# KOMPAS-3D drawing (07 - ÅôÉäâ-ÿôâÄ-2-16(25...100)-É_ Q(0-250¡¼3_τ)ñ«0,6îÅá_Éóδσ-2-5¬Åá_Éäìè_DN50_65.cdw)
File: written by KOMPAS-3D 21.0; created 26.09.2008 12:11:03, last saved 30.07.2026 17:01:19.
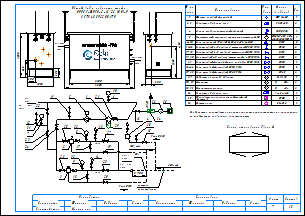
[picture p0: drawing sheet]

Sheets 1-2: A3, landscape

Document properties: Наименование: Макро:21; Автор: RaskoAdmin; Форматы листов документа: 2xA3; Полное имя файла: \\UR38nt01\Departments\КТО\КБ ПУРДГ\Заявки\Прайс-лист на типовые шкафы ГРПШ\ПУРДГ_стандарт_30_04_2026\ПУРДГ с РДНК\ПУРДГ-ШУГО-2-16(25...100)-Р_ Q(0-250нм3_ч)до0,6МПа_Рвых-2-5кПа_РДНК_DN50_65.cdw

Title block, sheet 1: Наименование: Пункт учета газа / ПУГ-Ш-400-Р / ЛГТИ.485922.001ТУ; designation: ЛГТИ.03.4411141; sheet number: 1; Количество листов документа: 2; organisation: ООО "ЭЛЬСТЕР Газэлектроника"; Форматы листов документа: A3; stored path: C:\Рабочие документы\Компас\ПУГ\Схема.cdw; Разработал: Устинов; Проверил: Кошкин; Утвердил: Кошкин
Title block, sheet 2: sheet number: 2; stored path: D:\Рабочие документы\Заявки\ПУРДГ\ПУРДГ-ШУЭО-2-100-Р 4411220.cdw; designation, second copy: ЛГТИ.03.4411141-

Views: Вид 1, Вид 2
Referenced files: wcvoit.frw
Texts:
  Normal
  № на
  схеме
  Усл.
  обозн.
  Марка
  (модель)
  Кол.
  Фильтр газовый фланцевый
  ФГ 16-50
  Регулятор давления газа
  РДНК-50
  Клапан предохранительный сбросной
  КПС DN20
  Измерительный комплекс с ротационным счетчиком Ду50
  СГ-ЭК-Р-(0,2...2,0)-
  Кран кнопочный VE-РАСКО-НЗ-1,6-G1/2-М20
  DN15
  Кран шаровой "под приварку" штуцерный DN20 PN16
  DN20
  Кран шаровой "под приварку" штуцерный DN15 PN16
  Кран шаровой "под приварку" штуцерный п/п DN15 PN16
  Кран шаровой фланцевый с мех. приводом DN50 PN16
  Кран шаровой фланцевый DN50 PN16
  Кран шаровой фланцевый DN65 PN16
  DN50
  DN65
  Индикатор перепада давления
  Манометр
  Манометр-напоромер
  Обогреватель газогорелочный шкафной
  (Эльтон")
  Счетчик газа
  Delta 15
  0...     МПа
  0...     кПа
  Venio-A-15
  ОГШН
  BK-G1,6
  Общий вид и габариты шкафа
  ПУРДГ-ШУГО-2-16(25...100)-Р
  Выход газа
  Вход газа
  logo-rasko-ge.png
  DN 1
  местное
  сопротивление
  Римп DN15
  Римп DN20
  Выход
  газа
  Р=     кПа
  Вход
  Р=       МПа
  PDI
  Схема открывания дверей
  Предприятие изготовитель может заменять комплектующие на аналогичные,
  не ухудшающие заявленных характеристик.
  Должность
  Конструктор
  Фамилия
  Подпись
  Дата
  Согласовано
  Максимкин
  Лист
  Листов
  POLYLINE_STYLE_0.18_RGB_0_0_0
  POLYLINE_STYLE_0.50_RGB_0_0_0
  POLYLINE_STYLE_0.34_RGB_0_0_0
  PHANTOM_RGB_0_0_0_SC_1_THICK_0.18
  K5LT_THIN_RGB_0_0_0_THICK_0.18
  K5LT32769_RGB_0_0_0_THICK_0.18
  K5LT12_RGB_0_0_0_SC_1_THICK_0.18
  K5LT_DASHED_RGB_0_0_0_SC_1_THICK_0.18
  ACISOTGL_RGB_0_0_0_SC_0.8_THICK_0.25
  CONTINUOUS_RGB_0_127_31_THICK_0.3
  CONTINUOUS_RGB_0_0_255_THICK_0.35
  CONTINUOUS_RGB_255_0_0_THICK_0.35
  POLYLINE_STYLE_0.25_RGB_0_0_0
  CONTINUOUS_RGB_0_0_0_THICK_0.5
  POLYLINE_STYLE_0.35_RGB_0_0_255
  CONTINUOUS_RGB_0_0_0_THICK_0.4
  CONTINUOUS_RGB_0_0_0_THICK_0.35
  НЕВИДИМАЯ_RGB_0_0_0_SC_0.3_THICK_0.25
  СONTINUOUS_RGB_0_0_0_THICK_0.25
  ОСЕВАЯ2_RGB_248_153_30_SC_0.3_THICK_0.25
  Без оформления
Dimensions and other numbers on the sheet: 1; 2, 3; 2; 4; 5; 6-10; 11-16; 6; 17, 18; 19, 20; 21; 22-26; 27, 28; 29; 30, 31; 32, 33; 34; 35; 36; 1500; 250; 300; 1050; 550; 305; 2300; 4130; 2000; 2600; 5,,,7DN 1; 7; 31; 12; 22; 23; 24; 11; 30; 25; 32; 8; 17; 13; 27; 19; 10; 15; 26; 33; 9; 3; 18; 14; 28; 20; 16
